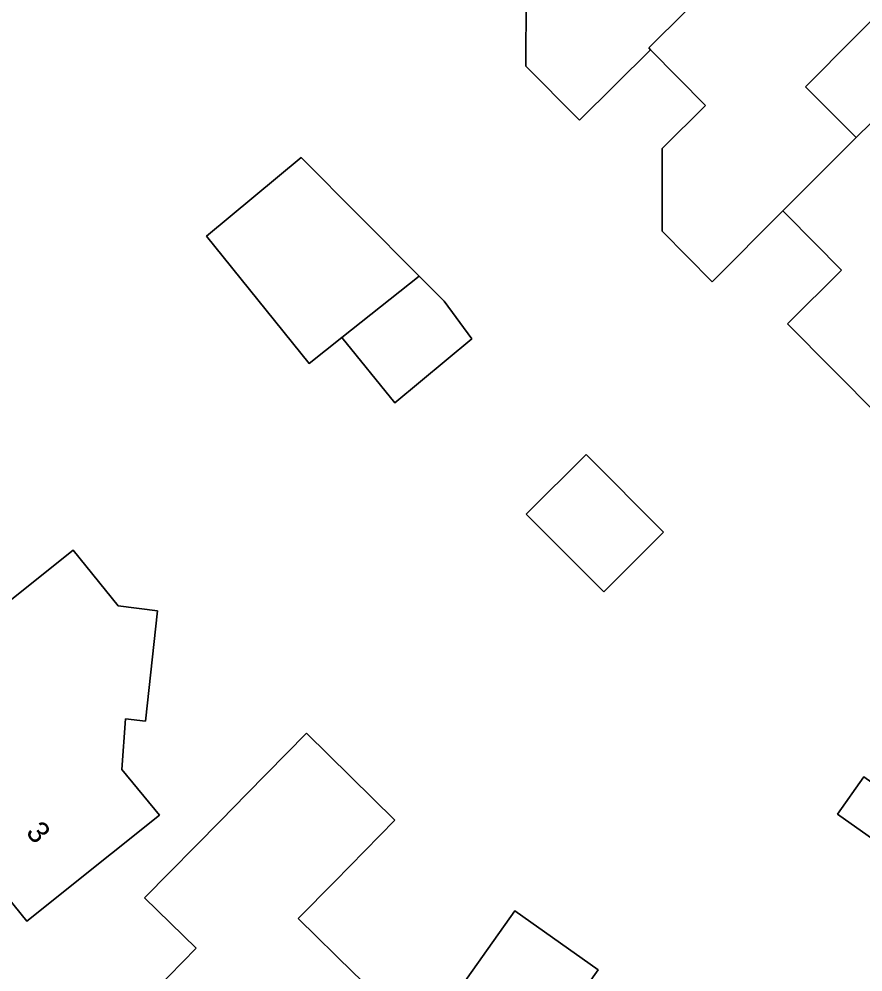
# Model space of a CAD drawing. Extents: x 159499 to 160349, y 382524 to 383273.
# Drawn here: x 160007.29 to 160046.07, y 383068.91 to 383112.66 of the extents above; entities that cross this region are included whole.
import ezdxf

# ---------------------------------------------------------------- set-up
doc = ezdxf.new("R2010")
doc.units = 0
for name, color, linetype in [('IMGEO_Erf', 7, 'Continuous'), ('IMGEO_Pand', 7, 'Continuous'), ('IMGEO_Pand_nummerreeks', 7, 'Continuous')]:
    doc.layers.add(name, color=color, linetype=linetype)

msp = doc.modelspace()

# ---------------------------------------------------------------- linework, layer by layer
at = {"layer": 'IMGEO_Erf'}
for points in [[(160047.989, 383114.149), (160043.439, 383109.554), (160045.76, 383107.219), (160047.17, 383108.6)], [(160046.784, 383094.465), (160042.61, 383098.674), (160045.095, 383101.138), (160042.56, 383103.694), (160042.399, 383103.856), (160039.147, 383100.602), (160036.843, 383102.926), (160036.851, 383106.723), (160038.846, 383108.701), (160036.311, 383111.257), (160033.044, 383108.018), (160032.964, 383108.099), (160030.58, 383110.504), (160030.598, 383113.675)]]:
    msp.add_lwpolyline(points, dxfattribs=at)
for points in [[(160024.556, 383095.037), (160022.131, 383098.046), (160020.621, 383096.851), (160015.912, 383102.694), (160020.255, 383106.302), (160025.683, 383100.858), (160025.793, 383100.748), (160026.825, 383099.713), (160028.1, 383097.98)], [(160034.162, 383086.359), (160030.598, 383089.93), (160033.35, 383092.676), (160036.913, 383089.105)], [(160011.843, 383085.728), (160013.657, 383085.494), (160013.102, 383080.419), (160012.189, 383080.526), (160012.019, 383078.201), (160013.746, 383076.102), (160011.54, 383074.345), (160007.652, 383071.248), (160005.568, 383073.804), (160003.777, 383074.045), (160004.319, 383079.118), (160005.233, 383079.064), (160005.425, 383080.99), (160003.591, 383083.329), (160007.496, 383086.453), (160009.78, 383088.28)], [(160022.671, 383068.85), (160024.677, 383066.95), (160021.981, 383064.293), (160018.479, 383060.723), (160012.296, 383066.782), (160015.426, 383069.997), (160013.053, 383072.305), (160016.56, 383075.87), (160017.742, 383077.071), (160020.5, 383079.875), (160024.568, 383075.873), (160021.809, 383073.069), (160020.124, 383071.356)], [(160047.613, 383074.239), (160044.902, 383076.154), (160046.114, 383077.869), (160048.825, 383075.954)], [(160031.769, 383065.99), (160036.505, 383062.644), (160033.333, 383058.153), (160030.448, 383054.068), (160024.953, 383057.978), (160027.292, 383061.298), (160028.107, 383062.455), (160025.273, 383064.419), (160024.441, 383063.269), (160024.22, 383063.429), (160027.105, 383067.514), (160030.074, 383071.719), (160033.905, 383069.012)]]:
    msp.add_lwpolyline(points, close=True, dxfattribs=at)
at = {"layer": 'IMGEO_Pand'}
for points in [[(160036.311, 383111.257), (160036.228, 383111.34), (160039.586, 383114.674), (160037.215, 383117.052), (160038.641, 383118.472), (160041.817, 383121.634), (160039.901, 383123.546), (160040.531, 383124.177), (160038.003, 383126.714), (160035.763, 383124.493), (160035.504, 383124.744), (160034.577, 383123.828), (160034.833, 383123.565), (160030.062, 383118.834), (160029.132, 383119.771), (160026.442, 383117.102), (160029.836, 383113.679), (160030.598, 383113.675), (160030.58, 383110.504), (160032.964, 383108.099), (160033.044, 383108.018)], [(160047.989, 383114.149), (160046.077, 383116.072), (160046.692, 383116.707), (160044.168, 383119.245), (160041.984, 383116.966), (160041.669, 383117.242), (160040.749, 383116.34), (160040.99, 383116.079), (160039.586, 383114.674), (160036.228, 383111.34), (160036.311, 383111.257), (160038.846, 383108.701), (160036.851, 383106.723), (160036.843, 383102.926), (160039.147, 383100.602), (160042.399, 383103.856), (160045.76, 383107.219), (160043.439, 383109.554)], [(160054.178, 383106.641), (160052.229, 383108.605), (160052.869, 383109.201), (160050.377, 383111.741), (160048.12, 383109.556), (160047.844, 383109.794), (160046.917, 383108.851), (160047.17, 383108.6), (160045.76, 383107.219), (160042.399, 383103.856), (160042.56, 383103.694), (160045.095, 383101.138), (160042.61, 383098.674), (160046.784, 383094.465), (160051.976, 383099.664), (160049.558, 383102.063), (160051.002, 383103.494)], [(160020.255, 383106.302), (160015.912, 383102.694), (160020.621, 383096.851), (160022.131, 383098.046), (160025.683, 383100.858)], [(160028.1, 383097.98), (160026.825, 383099.713), (160025.793, 383100.748), (160025.683, 383100.858), (160022.131, 383098.046), (160024.556, 383095.037)], [(160033.35, 383092.676), (160030.598, 383089.93), (160034.162, 383086.359), (160036.913, 383089.105)], [(160011.54, 383074.345), (160013.746, 383076.102), (160012.019, 383078.201), (160012.189, 383080.526), (160013.102, 383080.419), (160013.657, 383085.494), (160011.843, 383085.728), (160009.78, 383088.28), (160007.496, 383086.453), (160003.591, 383083.329), (160005.425, 383080.99), (160005.233, 383079.064), (160004.319, 383079.118), (160003.777, 383074.045), (160005.568, 383073.804), (160007.652, 383071.248)], [(160020.124, 383071.356), (160021.809, 383073.069), (160024.568, 383075.873), (160020.5, 383079.875), (160017.742, 383077.071), (160016.56, 383075.87), (160013.053, 383072.305), (160015.426, 383069.997), (160012.296, 383066.782), (160018.479, 383060.723), (160021.981, 383064.293), (160024.677, 383066.95), (160022.671, 383068.85)], [(160048.825, 383075.954), (160046.114, 383077.869), (160044.902, 383076.154), (160047.613, 383074.239)], [(160027.105, 383067.514), (160024.22, 383063.429), (160024.441, 383063.269), (160025.273, 383064.419), (160028.107, 383062.455), (160027.292, 383061.298), (160024.953, 383057.978), (160030.448, 383054.068), (160033.333, 383058.153), (160036.505, 383062.644), (160031.769, 383065.99), (160033.905, 383069.012), (160030.074, 383071.719)]]:
    msp.add_lwpolyline(points, close=True, dxfattribs=at)

# ---------------------------------------------------------------- texts
at = {"layer": 'IMGEO_Pand_nummerreeks'}
msp.add_text('3', height=1, rotation=309.6113, dxfattribs=at).set_placement((160007.57, 383075.3))

doc.saveas('drawing.dxf')
